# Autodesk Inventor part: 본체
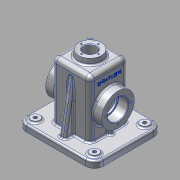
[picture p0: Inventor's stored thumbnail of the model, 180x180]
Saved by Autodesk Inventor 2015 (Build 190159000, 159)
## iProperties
Created: 2016-02
Part Number: 본체
Material: 알루미늄 6061
Document SubType Name: Modeling
Designer: Administrator
Density: 2.7 g/cm^3
Appearance: 알루미늄 - 평지
Mass: 883.249 g
Surface Area: 914.012 cm^2
Volume: 327.129 cm^3
Author: Administrator
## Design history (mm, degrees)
sketch "스케치7"
  geometry: L1 (32.5, 32.5)-(-32.5, 32.5); L2 (-32.5, 32.5)-(-32.5, -32.5); L3 (-32.5, -32.5)-(32.5, -32.5); L4 (32.5, -32.5)-(32.5, 32.5); L5 (32.5, 32.5)-(-32.5, -32.5); L6 (-32.5, 32.5)-(32.5, -32.5); 1 further point
  constraints: 12 end point, 2 midpoint, 2 parallel, 2 perpendicular, 1 horizontal
  dimensions: "d20" = 65 distance of L2.end L3.end
extrude "돌출6" new body sketch "스케치7" distance "d21" = 110; taper "d22" = 0 deg
fillet "모깎기2" dims "d23" = 8
fillet "모깎기3" dims "d24" = 8
feature "쉘1" dims "d25" = 5
sketch "스케치8"
  geometry: C1 r 20 at (0, 0); 1 further point
  constraints: 1 centre point, 1 coincident
  dimensions: "d26" = 40 diameter of C1
extrude "돌출7" join sketch "스케치8" distance "d27" = 10; taper "d28" = 0 deg
feature "면 기울기2" dims angle "d29" = 5 deg
sketch "스케치9"
  geometry: L1 (65, 57.5)-(-65, 57.5); L2 (-65, 57.5)-(-65, -57.5); L3 (-65, -57.5)-(65, -57.5); L4 (65, -57.5)-(65, 57.5); L5 (65, 57.5)-(-65, -57.5); L6 (-65, 57.5)-(65, -57.5); L7 (27.5, -24.5)-(27.5, 24.5) reference; L8 (24.5, 27.5)-(-24.5, 27.5) reference; L9 (-27.5, 24.5)-(-27.5, -24.5) reference; L10 (-24.5, -27.5)-(24.5, -27.5) reference; L11 (24.5, -32.5)-(-24.5, -32.5) reference; L12 (-32.5, -24.5)-(-32.5, 24.5) reference; L13 (-24.5, 32.5)-(24.5, 32.5) reference; L14 (32.5, 24.5)-(32.5, -24.5) reference; A1 r 3 centre (24.5, -24.5) between (24.5, -27.5) and (27.5, -24.5) reference; A2 r 3 centre (24.5, 24.5) between (27.5, 24.5) and (24.5, 27.5) reference; A3 r 3 centre (-24.5, 24.5) between (-24.5, 27.5) and (-27.5, 24.5) reference; A4 r 3 centre (-24.5, -24.5) between (-27.5, -24.5) and (-24.5, -27.5) reference; A5 r 8 centre (24.5, -24.5) between (24.5, -32.5) and (32.5, -24.5) reference; A6 r 8 centre (-24.5, -24.5) between (-32.5, -24.5) and (-24.5, -32.5) reference; A7 r 8 centre (-24.5, 24.5) between (-24.5, 32.5) and (-32.5, 24.5) reference; A8 r 8 centre (24.5, 24.5) between (32.5, 24.5) and (24.5, 32.5) reference; 1 further point
  constraints: 12 end point, 2 midpoint, 2 parallel, 1 horizontal, 1 perpendicular
  dimensions: "d30" = 130 distance of L2.end L3.end; "d31" = 115 distance of L1.end L2.end
extrude "돌출8" join sketch "스케치9" distance "d32" = 13; taper "d33" = 0 deg
fillet "모깎기4" dims "d34" = 15
sketch "스케치11"
  geometry: L1 (110, 24.5)-(110, 20) reference; L2 (110, 20)-(120, 19.125) reference; L3 (120, 19.125)-(120, -19.125) reference; L4 (120, -19.125)-(110, -20) reference; L5 (110, -20)-(110, -24.5) reference; L6 (102, -32.5)-(13, -32.5) reference; L7 (13, -57.5)-(0, -57.5) reference; L8 (13, 57.5)-(13, 32.5) reference; L9 (0, -27.5)-(102, -27.5) reference; L10 (105, -24.5)-(105, 24.5) reference; L11 (102, 27.5)-(0, 27.5) reference; L12 (13, -32.5)-(13, -57.5) reference; L13 (0, 57.5)-(13, 57.5) reference; L14 (13, 32.5)-(102, 32.5) reference; L15 (98.069, 32.5)-(13, 47.5); L16 (13, 47.5)-(13, 32.5); L17 (13, 32.5)-(98.069, 32.5); L18 (0, 0)-(66.088, 0); L19 (13, -32.5)-(98.069, -32.5); L20 (98.069, -32.5)-(13, -47.5); L21 (13, -47.5)-(13, -32.5); L22 (0, -57.5)-(0, -27.5) reference; L23 (0, 27.5)-(0, 57.5) reference; A1 r 8 centre (102, 24.5) between (110, 24.5) and (102, 32.5) reference; A2 r 8 centre (102, -24.5) between (102, -32.5) and (110, -24.5) reference; A3 r 3 centre (102, -24.5) between (102, -27.5) and (105, -24.5) reference; A4 r 3 centre (102, 24.5) between (105, 24.5) and (102, 27.5) reference
  constraints: 14 end point, 3 symmetric about line, 2 collinear, 1 horizontal, 1 perpendicular, 1 vertical
  dimensions: "d38" = 10 deg angle of L13 L15; "d39" = 10 distance from line of L13 L15.end
extrude "돌출10" join sketch "스케치11" stored distance "d40" = 10; taper "d41" = 0 deg
sketch "스케치12"
  geometry: L1 (65, 42.5)-(65, -42.5) reference; L2 (50, -57.5)-(-50, -57.5) reference; L3 (-65, -42.5)-(-65, 42.5) reference; L4 (-50, 57.5)-(50, 57.5) reference; L5 (24.5, 27.5)-(-24.5, 27.5) reference; L6 (-27.5, 24.5)-(-27.5, -24.5) reference; L7 (-24.5, -27.5)-(24.5, -27.5) reference; L8 (27.5, -24.5)-(27.5, 24.5) reference; L9 (60, -42.5)-(60, 42.5); L10 (50, 52.5)-(-50, 52.5); L11 (-60, 42.5)-(-60, -42.5); L12 (-50, -52.5)-(50, -52.5); A1 r 15 centre (50, 42.5) between (65, 42.5) and (50, 57.5) reference; A2 r 15 centre (50, -42.5) between (50, -57.5) and (65, -42.5) reference; A3 r 15 centre (-50, -42.5) between (-65, -42.5) and (-50, -57.5) reference; A4 r 15 centre (-50, 42.5) between (-50, 57.5) and (-65, 42.5) reference; A5 r 3 centre (24.5, 24.5) between (27.5, 24.5) and (24.5, 27.5) reference; A6 r 3 centre (-24.5, 24.5) between (-24.5, 27.5) and (-27.5, 24.5) reference; A7 r 3 centre (-24.5, -24.5) between (-27.5, -24.5) and (-24.5, -27.5) reference; A8 r 3 centre (24.5, -24.5) between (24.5, -27.5) and (27.5, -24.5) reference; A9 r 10 centre (50, 42.5) between (60, 42.5) and (50, 52.5); A10 r 10 centre (-50, 42.5) between (-50, 52.5) and (-60, 42.5); A11 r 10 centre (-50, -42.5) between (-60, -42.5) and (-50, -52.5); A12 r 10 centre (50, -42.5) between (50, -52.5) and (60, -42.5); 1 further point
  constraints: 8 end point, 8 point on circle, 4 centre point, 7 other
  dimensions: "d42" = 5 distance between parallel lines of L1 L9
extrude "돌출11" cut sketch "스케치12" distance "d43" = 2; taper "d44" = 0 deg
node "작업 평면1"
sketch "스케치13"
  geometry: L1 (24.5, -47)-(24.5, -102); C1 r 27.5 at (24.5, -47)
  constraints: 2 end point, 1 centre point, 1 vertical
  dimensions: "d46" = 55 distance of L1.start L1.end; "d47" = 55 diameter of C1
extrude "돌출12" join sketch "스케치13" stored distance "d48" = 2; taper "d49" = 0 deg
sketch "스케치14"
  geometry: L1 (-24.5, 110)-(-20, 110) reference; L2 (-20, 110)-(-19.125, 120) reference; L3 (-19.125, 120)-(19.125, 120) reference; L4 (19.125, 120)-(20, 110) reference; L5 (20, 110)-(24.5, 110) reference; L6 (32.5, 102)-(32.5, 82.5) reference; L7 (32.5, 82.5)-(47.5, 82.5) reference; L8 (47.5, 82.5)-(47.5, 27.5) reference; L9 (47.5, 27.5)-(32.5, 27.5) reference; L10 (32.5, 27.5)-(32.5, 13) reference; L11 (32.5, 13)-(65, 13) reference; L12 (65, 13)-(65, 2) reference; L13 (65, 2)-(60, 2) reference; L14 (60, 2)-(60, 0) reference; L15 (60, 0)-(27.5, 0) reference; L16 (27.5, 0)-(27.5, 102) reference; L17 (24.5, 105)-(-24.5, 105) reference; L18 (-27.5, 102)-(-27.5, 0) reference; L19 (-27.5, 0)-(-60, 0) reference; L20 (-60, 0)-(-60, 2) reference; L21 (-60, 2)-(-65, 2) reference; L22 (-65, 2)-(-65, 13) reference; L23 (-65, 13)-(-32.5, 13) reference; L24 (-32.5, 13)-(-32.5, 102) reference; L25 (32.5, 13)-(32.5, 37.5); L26 (32.5, 13)-(37.5, 13); L27 (37.5, 13)-(37.5, 37.5); L28 (37.5, 37.5)-(32.5, 37.5); A1 r 8 centre (-24.5, 102) between (-24.5, 110) and (-32.5, 102) reference; A2 r 8 centre (24.5, 102) between (32.5, 102) and (24.5, 110) reference; A3 r 3 centre (24.5, 102) between (27.5, 102) and (24.5, 105) reference; A4 r 3 centre (-24.5, 102) between (-24.5, 105) and (-27.5, 102) reference; 2 further points
  constraints: 8 end point, 2 collinear, 2 point on line, 1 parallel, 1 perpendicular
  dimensions: "d73" = 10 distance between parallel lines of L16 L27; "d74" = 10 distance between parallel lines of L28 L9
extrude "돌출13" join sketch "스케치14" stored distance "d51" = 6; taper "d52" = 0 deg
sketch "스케치15"
  geometry: L1 (-65, -42.5)-(-65, 42.5) reference; L2 (-50, 57.5)-(50, 57.5) reference; L3 (65, 42.5)-(65, -42.5) reference; L4 (50, -57.5)-(-50, -57.5) reference; L5 (-24.5, -27.5)-(24.5, -27.5) reference; L6 (27.5, -24.5)-(27.5, 24.5) reference; L7 (24.5, 27.5)-(-24.5, 27.5) reference; L8 (-27.5, 24.5)-(-27.5, -24.5) reference; L9 (-32.5, -24.5)-(-32.5, 24.5) reference; L10 (-24.5, 32.5)-(-5, 32.5) reference; L11 (-5, 32.5)-(-5, 47.5) reference; L12 (-5, 47.5)-(5, 47.5) reference; L13 (5, 47.5)-(5, 32.5) reference; L14 (5, 32.5)-(24.5, 32.5) reference; L15 (32.5, 24.5)-(32.5, 3) reference; L16 (32.5, 3)-(37.5, 3) reference; L17 (37.5, -3)-(32.5, -3) reference; L18 (32.5, -3)-(32.5, -24.5) reference; L19 (24.5, -32.5)-(5, -32.5) reference; L20 (5, -32.5)-(5, -47.5) reference; L21 (5, -47.5)-(-5, -47.5) reference; L22 (-5, -47.5)-(-5, -32.5) reference; L23 (-5, -32.5)-(-24.5, -32.5) reference; L24 (37.5, 3)-(37.5, -3) reference; C1 r 7.5 at (-50, -42.5); C2 r 7.5 at (-50, 42.5); C3 r 7.5 at (50, 42.5); C4 r 7.5 at (50, -42.5); A1 r 15 centre (-50, 42.5) between (-50, 57.5) and (-65, 42.5) reference; A2 r 15 centre (50, 42.5) between (65, 42.5) and (50, 57.5) reference; A3 r 15 centre (50, -42.5) between (50, -57.5) and (65, -42.5) reference; A4 r 15 centre (-50, -42.5) between (-65, -42.5) and (-50, -57.5) reference; A5 r 3 centre (-24.5, -24.5) between (-27.5, -24.5) and (-24.5, -27.5) reference; A6 r 3 centre (24.5, -24.5) between (24.5, -27.5) and (27.5, -24.5) reference; A7 r 3 centre (24.5, 24.5) between (27.5, 24.5) and (24.5, 27.5) reference; A8 r 3 centre (-24.5, 24.5) between (-24.5, 27.5) and (-27.5, 24.5) reference; A9 r 8 centre (-24.5, -24.5) between (-32.5, -24.5) and (-24.5, -32.5) reference; A10 r 8 centre (-24.5, 24.5) between (-24.5, 32.5) and (-32.5, 24.5) reference; A11 r 8 centre (24.5, 24.5) between (32.5, 24.5) and (24.5, 32.5) reference; A12 r 8 centre (24.5, -24.5) between (24.5, -32.5) and (32.5, -24.5) reference; 1 further point
  constraints: 4 centre point, 4 coincident, 3 equal radius
  dimensions: "d53" = 15 diameter of C1
extrude "돌출14" join sketch "스케치15" distance "d54" = 3; taper "d55" = 0 deg
sketch "스케치16"
  geometry: L1 (25.5, -70)-(74.5, -70) reference; L2 (77.5, -67)-(77.5, -18) reference; L3 (74.5, -15)-(25.5, -15) reference; L4 (22.5, -18)-(22.5, -67) reference; L5 (17.5, -67)-(17.5, -18) reference; L6 (25.5, -10)-(45, -10) reference; L7 (45, -10)-(45, 4.471) reference; L8 (45, 4.471)-(55, 4.471) reference; L9 (55, 4.471)-(55, -10) reference; L10 (55, -10)-(74.5, -10) reference; L11 (82.5, -18)-(82.5, -39.5) reference; L12 (82.5, -39.5)-(87.5, -39.5) reference; L13 (87.5, -45.5)-(82.5, -45.5) reference; L14 (82.5, -45.5)-(82.5, -67) reference; L15 (74.5, -75)-(55, -75) reference; L16 (55, -75)-(55, -89.471) reference; L17 (55, -89.471)-(45, -89.471) reference; L18 (45, -89.471)-(45, -75) reference; L19 (45, -75)-(25.5, -75) reference; L20 (87.5, -39.5)-(87.5, -45.5) reference; C1 r 7.5 at (100, 0) reference; C2 r 7.5 at (0, -85) reference; C3 r 7.5 at (0, 0) reference; C4 r 7.5 at (100, -85) reference; A1 r 3 centre (25.5, -67) between (22.5, -67) and (25.5, -70) reference; A2 r 3 centre (74.5, -67) between (74.5, -70) and (77.5, -67) reference; A3 r 3 centre (74.5, -18) between (77.5, -18) and (74.5, -15) reference; A4 r 3 centre (25.5, -18) between (25.5, -15) and (22.5, -18) reference; A5 r 8 centre (25.5, -67) between (17.5, -67) and (25.5, -75) reference; A6 r 8 centre (25.5, -18) between (25.5, -10) and (17.5, -18) reference; A7 r 8 centre (74.5, -18) between (82.5, -18) and (74.5, -10) reference; A8 r 8 centre (74.5, -67) between (74.5, -75) and (82.5, -67) reference; 1 further point
hole "구멍1" sketch "스케치16" at (0, 0), (100, 0), (100, -85), (0, -85) diameter "d56" = 6; stored, may be unused: countersink angle "d60" = 90 deg, drill point angle "d62" = 118 deg; dims "d57" = 6, "d58" = 4, "d59" = 2, "d61" = 8
hole "구멍2" diameter "d65" = 30; stored, may be unused: countersink angle "d69" = 90 deg, drill point angle "d71" = 118 deg; dims "d63" = 10, "d64" = 10, "d66" = 6, "d67" = 35, "d68" = 17, "d70" = 8
fillet "모깎기11" dims "d80" = 3
hole "구멍3" diameter "d83" = 21; stored, may be unused: countersink angle "d87" = 90 deg, drill point angle "d89" = 118 deg; dims "d81" = 10, "d82" = 10, "d84" = 6, "d85" = 35, "d86" = 17, "d88" = 8
fillet "모깎기12" dims "d90" = 3
chamfer "모따기1" distance "d91" = 1; stored, may be unused: second distance "d92" = 2, angle "d93" = 45 deg
fillet "모깎기13" dims "d94" = 0.3
fillet "모깎기14" dims "d95" = 3
sketch "스케치17"
  geometry: L1 (0, 0)-(0, -14.5); 1 further point
  constraints: 2 end point, 1 coincident, 1 vertical
  dimensions: "d96" = 14.5 distance of L1.start L1.end
hole "구멍4" sketch "스케치17" at (0, -14.5) diameter "d97" = 2.459; stored, may be unused: countersink angle "d101" = 90 deg, drill point angle "d103" = 118 deg; dims "d98" = 7, "d99" = 35, "d100" = 17, "d102" = 9
sketch "스케치18"
  geometry: L1 (0, 0)-(0, 21); C1 r 27.5 at (0, 0) reference; 2 further points
  constraints: 2 end point, 1 coincident, 1 vertical
  dimensions: "d107" = 21 distance of L1.start L1.end
hole "구멍5" sketch "스케치18" at (0, 21) diameter "d108" = 3.242; stored, may be unused: countersink angle "d112" = 90 deg, drill point angle "d114" = 118 deg; dims "d109" = 8, "d110" = 35, "d111" = 17, "d113" = 10
node "작업 평면2"
sketch "스케치19"
  geometry: L1 (43.625, 18)-(5.375, 18) reference; L2 (-8, 0)-(-8, -89) reference; 3 further points
  constraints: 1 other
  dimensions: "d119" = 26 distance from line of L1 point (24.5, -8); "d120" = 32.5 distance from line of point (24.5, -8) L2
feature "엠보싱1" sketch "스케치19" dims "d121" = 0.5, "d122" = 0
fillet "모깎기15" dims "d123" = 3
fillet "모깎기16" dims "d124" = 3
fillet "모깎기17" dims "d125" = 3
fillet "모깎기18" dims "d126" = 3
fillet "모깎기19" dims "d127" = 3
node "솔리드2"
mirror "대칭2"
mirror "대칭3"
pattern_circular "원형 패턴1" dims angle "d105" = 360 deg
pattern_circular "원형 패턴2" dims angle "d116" = 360 deg
mirror "대칭4"
pattern_circular "원형 패턴3" dims angle "d129" = 360 deg
node "절단 모서리 투영2"
node "절단 모서리 투영4"
node "절단 모서리 투영5"
node "절단 모서리 투영6"
node "절단 모서리 투영7"
node "절단 모서리 투영8"
other parameters: "d45" = 15
